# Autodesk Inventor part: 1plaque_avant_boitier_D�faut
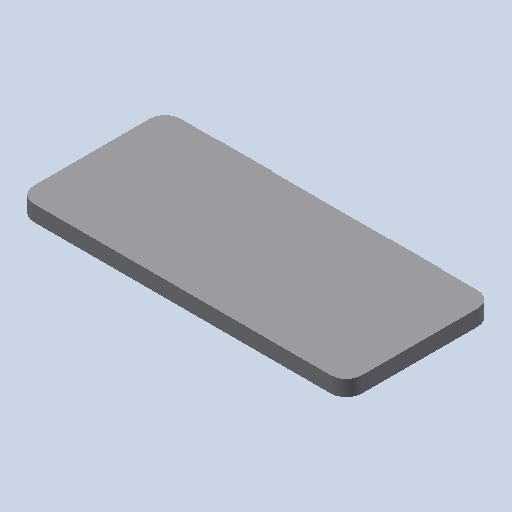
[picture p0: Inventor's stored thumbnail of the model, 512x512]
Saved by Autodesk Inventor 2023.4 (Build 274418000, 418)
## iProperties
Created: 2011-01
Part Number: 1plaque_avant_boitier_D�faut
Document SubType Name: Modeling
Designer: eric
Density: 1 g/cm^3
Mass: 5.23283 g
Surface Area: 40.173 cm^2
Volume: 5.23283 cm^3
Material: Générique
Appearance: Par défaut
Author: eric
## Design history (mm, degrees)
feature "Base1"
node "Corps solides"
node "Corps surfaciques"
node "Solide1"
